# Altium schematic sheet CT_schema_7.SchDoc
size 372 x 245 mm
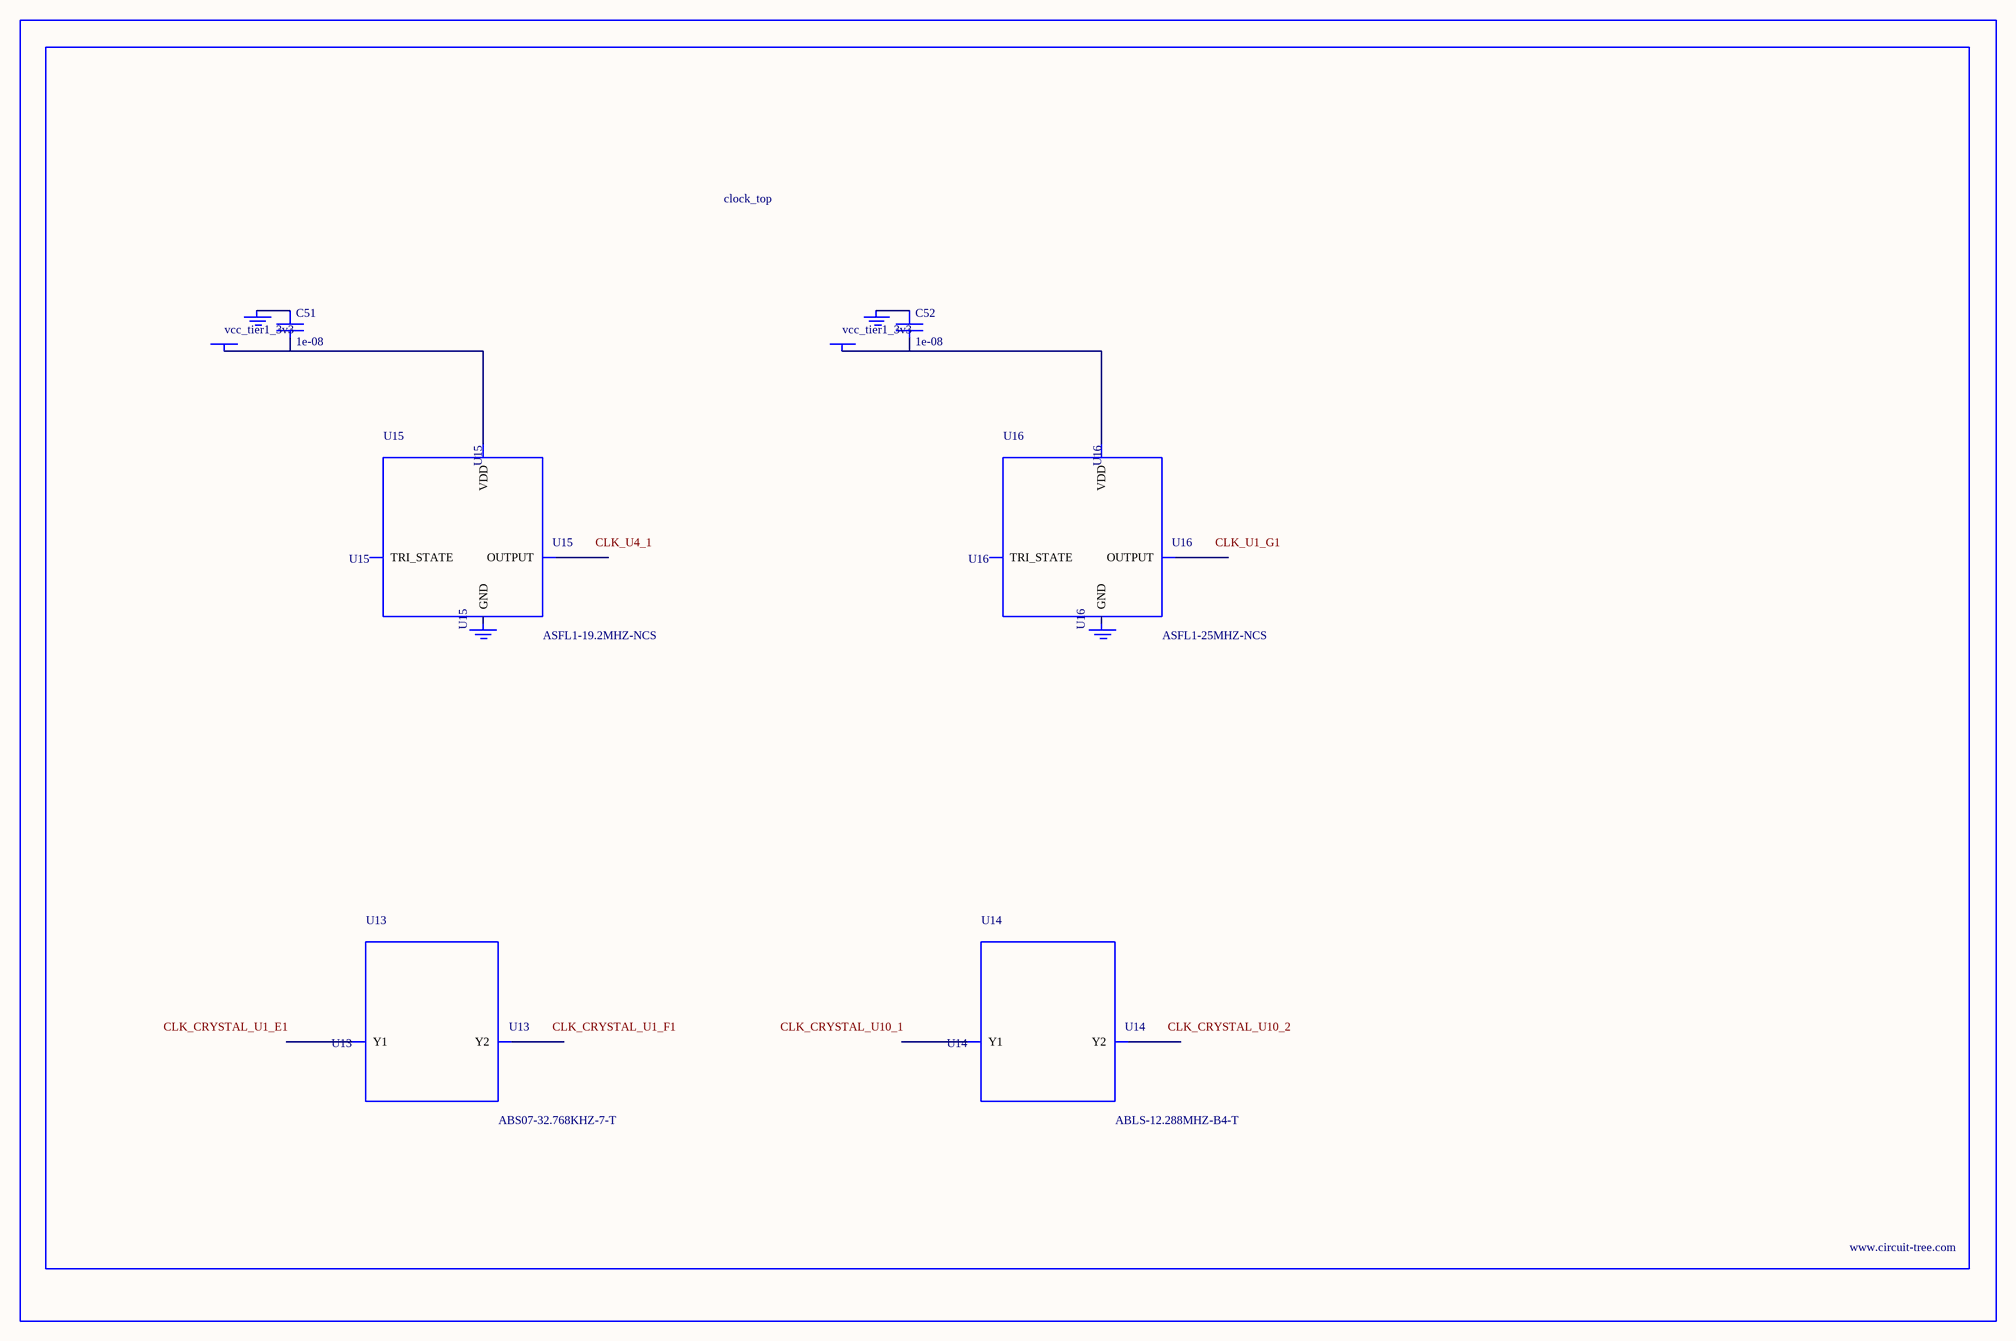
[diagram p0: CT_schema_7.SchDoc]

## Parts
BORDER6  (no value)
C51  1e-08  [C0402]
C52  1e-08  [C0402]
GND_INSTANCE_6_0  (no value)
GND_INSTANCE_6_1  (no value)
GND_INSTANCE_6_2  (no value)
GND_INSTANCE_6_3  (no value)
POWER_INSTANCE_6_0  vcc_tier1_3v3
POWER_INSTANCE_6_1  vcc_tier1_3v3
U13  ABS07-32.768KHZ-7-T  [ABS07-32.768KHZ-7-T]
U14  ABLS-12.288MHZ-B4-T  [ABLS-12.288MHZ-B4-T]
U15  ASFL1-19.2MHZ-NCS  [ASFL1]
U16  ASFL1-25MHZ-NCS  [ASFL1]

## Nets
NetC51_1: C51.1 GND_INSTANCE_6_0.0(GND)
NetC51_2: C51.2 POWER_INSTANCE_6_0.0(PWR) U15.4(VDD)
NetC52_1: C52.1 GND_INSTANCE_6_2.0(GND)
NetC52_2: C52.2 POWER_INSTANCE_6_1.0(PWR) U16.4(VDD)

Not connected (* = marked no-connect by the designer): GND_INSTANCE_6_1 0(GND); GND_INSTANCE_6_3 0(GND); U13 1(Y1) 2(Y2); U14 1(Y1) 2(Y2); U15 1(TRI_STATE) 2(GND) 3(OUTPUT); U16 1(TRI_STATE) 2(GND) 3(OUTPUT)

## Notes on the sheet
- Labels drawn without touching a wire or pin: CLK_CRYSTAL_U1_E1, CLK_CRYSTAL_U1_F1, CLK_CRYSTAL_U10_1, CLK_CRYSTAL_U10_2, CLK_U1_G1, CLK_U4_1

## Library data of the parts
BORDER6 = BORDER_PAGE6
C51 C52 = C0402C103K3RAC
GND_INSTANCE_6_0-GND_INSTANCE_6_3 = GND
POWER_INSTANCE_6_0 POWER_INSTANCE_6_1 = PWR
